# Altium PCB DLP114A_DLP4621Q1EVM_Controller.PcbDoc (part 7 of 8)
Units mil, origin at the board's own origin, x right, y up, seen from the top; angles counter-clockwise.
Board outline 4803.15 x 2598.43 mil, 14 copper layers (Top Layer, GND 1, SIGNAL 1, GND 2, SIGNAL 2, PWR SPLIT PLANE 1, GND 3, GND 4, PWR SPLIT PLANE 2, SIGNAL 3, GND 5, SIGNAL 4, GND 6, Bottom Layer), stack 91.4 mil thick; 489 components, 394 nets, 1925 pads, 1273 vias.
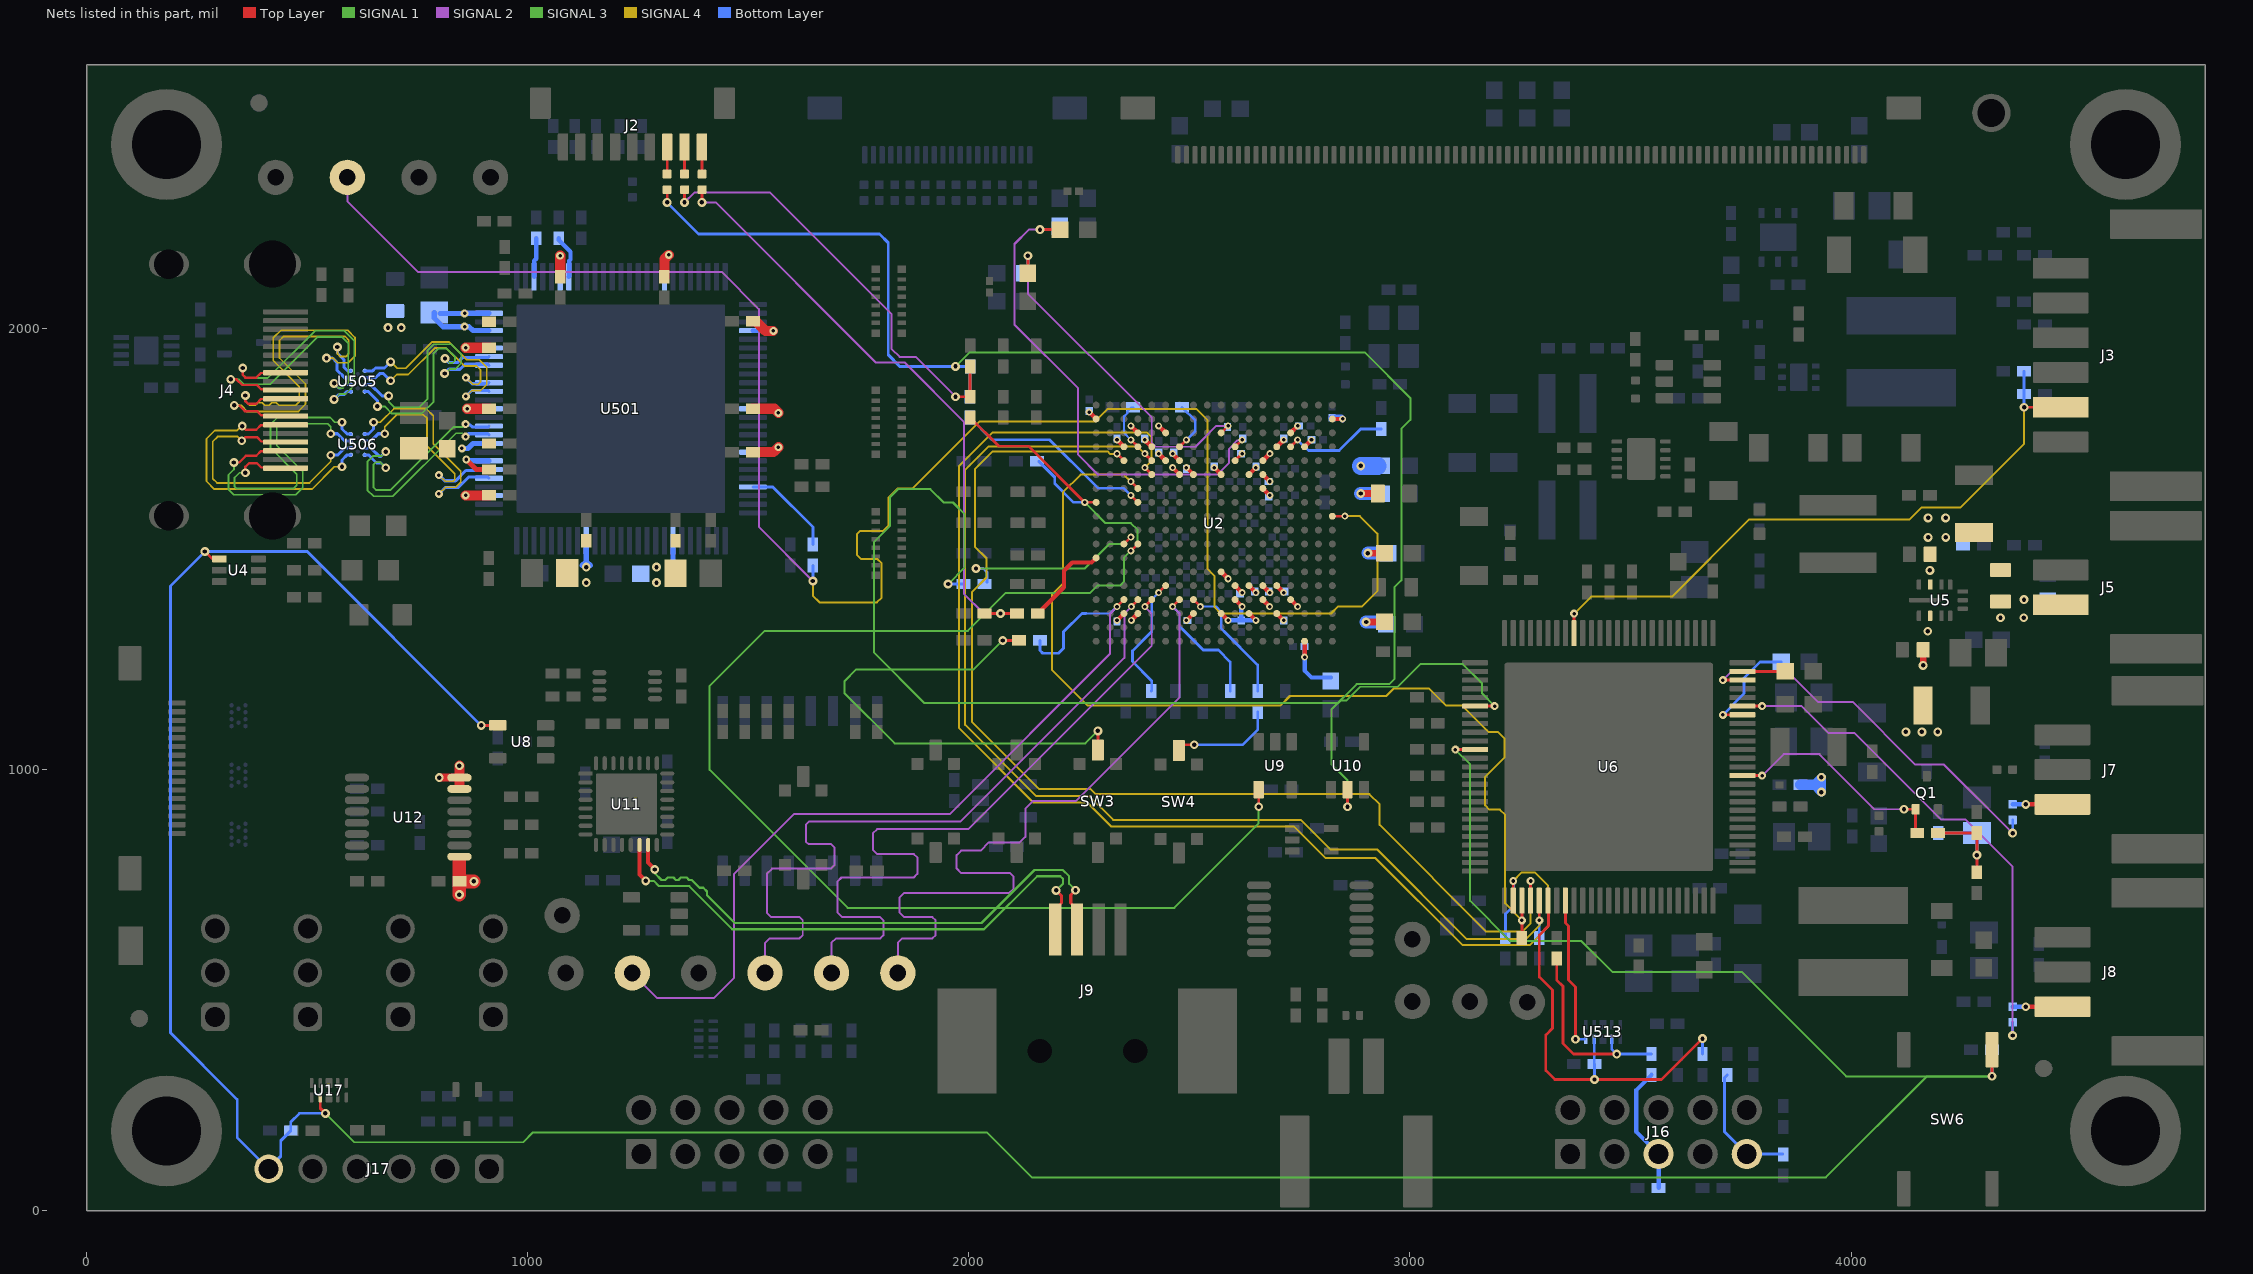
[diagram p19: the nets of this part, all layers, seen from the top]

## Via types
v1: diameter 20, hole 10, Top Layer to Bottom Layer, tented top, 716 vias
v2: diameter 16, hole 8, Top Layer to Bottom Layer, 234 vias
v3: diameter 19.68, hole 7.87, Top Layer to Bottom Layer, 170 vias
v4: diameter 18, hole 8, Top Layer to Bottom Layer, tented top, 78 vias
v5: diameter 18, hole 8, Top Layer to Bottom Layer, tented bottom, 51 vias
v6: diameter 39.37, hole 19.68, Top Layer to Bottom Layer, 24 vias

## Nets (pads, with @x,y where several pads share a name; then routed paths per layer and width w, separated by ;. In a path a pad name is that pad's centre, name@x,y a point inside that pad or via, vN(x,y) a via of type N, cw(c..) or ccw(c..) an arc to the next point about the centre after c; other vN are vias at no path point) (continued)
PMIC_SPI2_CSZ0: U6.33 U513.5 | length 344.7
  Top Layer w6.3: U6.33@3352.25,703.17 3352.25,652.44 3359.35,645.34 3359.35,523 3375.12,507.23 v1(3375.12,388.98)
  Bottom Layer w6.3: v1(3375.12,388.98) U513.5@3396.16,388.98
PMIC_SPI2_CSZ_S: C624.1 J16.9 R588.1 | length 284.7
  Bottom Layer w6.3: R588.1@3719.2,308.17 3712.85,301.82 3712.85,179.37 J16.9@3763.48,128.74 C624.1@3845.19,128.74
PMIC_SPI2_PICO: R589.2 R591.2 U6.31 U513.4 | length 941.5
  Top Layer w6.3: U6.31@3312.88,703.17 3313.78,702.26 3313.78,667.57 3314.07,667.29 3314.07,646.18 3293.19,625.31 3293.19,530.39 3323.18,500.4 3323.18,413.85 3307.98,398.66 3307.98,318.07 3328.33,297.72 v1(3418.39,297.72) 3570.45,297.72 v1(3663.2,390.47)
  Bottom Layer w6.3: U513.4@3417.86,388.98 3417.86,369.98 3417.86,333.3 R591.2@3418.39,332.78 v1(3418.39,297.72) ; R589.2@3663.2,355.41 v1(3663.2,390.47)
PMIC_SPI2_POCI: R62.1 R587.2 U513.2 | length 447.4
  Top Layer w6.3: R62.1@3332.56,571.67 3332.56,523.2 3346.58,509.18 3346.58,379.28 3370.44,355.42 v1(3468.88,355.42)
  Bottom Layer w6.3: U513.2@3457.23,388.98 3457.23,367.07 v1(3468.88,355.42) R587.2@3547.48,355.42
PMIC_SPI2_POCI_S: C628.1 J16.5 R587.1 | length 291.1
  Bottom Layer w10: R587.1@3547.48,308.17 3513.29,273.98 3513.29,178.93 J16.5@3563.48,128.74 C628.1@3563.48,52.01
PMIC_SPI_CLK: R575.2 U2.F5 U6.27 | length 3093.6
  Top Layer w6.3: v2(2398.81,1684.87) U2.F5@2414.56,1669.12 ; U6.27@3234.14,703.17 v4(3234.14,747.7)
  SIGNAL 4 w4.5: v2(2398.81,1684.87) 2414.56,1700.62 2414.56,1753.68 2404.27,1763.97 2053.39,1763.97 1978.03,1688.61 1978.03,1094.02 2146.35,925.71 2268.64,925.71 2323.34,871.01 2737.3,871.01 2808.62,799.69 2921.85,799.69 3119.2,602.34 3271.15,602.34 3313.41,644.59 3313.41,736.48 3282.72,767.17 3253.61,767.17 v4(3234.14,747.7)
  Bottom Layer w6.3: R575.2@3216.44,618.91 3216.44,673.27 3234.53,691.36 3234.53,747.3 v4(3234.14,747.7)
PMIC_SPI_CSZ0: R61.2 U2.G4 U6.28 | length 2297.4
  Top Layer w6.3: v2(2367.31,1653.38) U2.G4@2383.06,1637.63 ; R61.2@3253.82,618.91 v4(3253.82,658.64) U6.28@3253.82,703.17
  SIGNAL 4 w4.5: v2(2367.31,1653.38) 2351.55,1669.14 2253.45,1669.14 2213.22,1628.91 2213.22,1421.85 2188.15,1396.78 2188.15,1227.05 2269.71,1145.49 2706.38,1145.49 2727.98,1167.09 2945.74,1167.09 2962.6,1183.95 3043.48,1183.95 3082.07,1145.35 3118.22,1145.35 3178.36,1085.22 3199.78,1085.22 3213.78,1071.21 3213.78,1027.3 3170.14,983.66 3170.14,919.07 3179.75,909.45 3203.57,909.45 3215.56,897.47 3215.56,696.9 v4(3253.82,658.64)
PMIC_SPI_PICO: R574.2 U2.E5 U6.30 | length 2647.3
  Top Layer w6.3: v2(2398.81,1716.37) U2.E5@2414.56,1700.62 ; v4(3293.19,658.64) U6.30@3293.19,703.17
  SIGNAL 4 w4.5: v2(2398.81,1716.37) 2382.76,1732.42 2044.37,1732.42 1991.58,1679.63 1991.58,1101.7 2152.99,940.29 2273.36,940.29 2327.16,886.49 2752.05,886.49 2819.33,819.22 2925.23,819.22 3127.87,616.58 3263.22,616.58 3293.19,646.55 v4(3293.19,658.64)
  Bottom Layer w6.3: R574.2@3293.19,618.91 v4(3293.19,658.64)
PMIC_SPI_POCI: U2.E3 U6.29 | length 2598.8
  Top Layer w6.3: v2@2335.89,1716.23 U2.E3@2351.5,1700.62 ; U6.29@3273.51,703.17 v4(3273.51,747.7)
  SIGNAL 4 w4.5: v2(2335.82,1716.23) 2319.67,1716.23 2314.47,1721.43 2053.99,1721.43 2013.74,1681.18 2013.74,1505.42 2040,1479.15 2040,1435.74 2007.24,1402.98 2007.24,1108 2159.16,956.08 2276.05,956.08 2287.58,944.55 2908.07,944.55 2930.99,921.63 2930.99,874.82 3172.18,633.63 3255.6,633.63 3273.7,651.73 v4@3273.7,747.51
PMIC_TIA_PD1: L525.1 U6.73 | length 891.3
  Top Layer w6.3: v4(3709.3,1203.17) U6.73@3753.82,1203.17
  SIGNAL 2 w4.5: v4(3709.3,1203.17) 3728.98,1222.85 3855.64,1222.85 3924.74,1153.75 4003.55,1153.75 4145.57,1011.73 4210.64,1011.73 v1(4366.2,856.17)
  Bottom Layer w6.3: v1(4366.2,856.17) L525.1@4366.19,886.04
PMIC_TIA_PD1_FILT: C39.1 U6.74 | length 97
  Top Layer w6.3: U6.74@3753.82,1222.85 C39.1@3850.84,1222.85
PMIC_TIA_PD2: L526.1 U6.70 | length 1175.4
  Top Layer w6.3: U6.70@3753.82,1144.11 v4(3798.35,1144.11)
  SIGNAL 2 w4.5: v4(3798.35,1144.11) 3888.03,1144.11 3949.16,1082.98 4008.06,1082.98 4203.35,887.68 4258.35,887.68 4366.13,779.9 v1(4366.13,397.48)
  Bottom Layer w6.3: v1(4366.13,397.48) L526.1@4366.11,427.36
PMIC_TIA_PD2_FILT: C589.1 U6.69 | length 247.3
  Top Layer w6.3: v4(3709.3,1124.43) U6.69@3753.82,1124.43
  Bottom Layer w6.3: v4(3709.3,1124.43) 3757.37,1172.51 3757.37,1207.89 3793.88,1244.4 C589.1@3841.62,1244.4
PMIC_VIN_N8V: Q1.1 R55.1 U6.62 | length 519.5
  Top Layer w6.3: U6.62@3753.82,986.63 v4(3798.35,986.63) ; v1(4119.86,910.37) Q1.1@4146.11,910.37 4146.11,860.55 R55.1@4150.05,856.62
  SIGNAL 2 w4.5: v4(3798.35,986.63) 3846.87,1035.15 3928.07,1035.15 4052.85,910.37 v1(4119.86,910.37)
PMIC_WD1: R546.2 U6.6 | length 2365
  Top Layer w6.3: U6.6@3147.52,1144.11 v4(3192.05,1144.11)
  SIGNAL 1 w4.5: v1(1953.03,1420.91) 1990.67,1458.55 1990.67,1579.1 1964.04,1605.73 1943.34,1605.73 1912.99,1636.08 1839.37,1636.08 1821.54,1618.24 1821.54,1553.16 1785.09,1516.71 1785.09,1265.51 1899.38,1151.22 2837.17,1151.22 2842.75,1156.8 2855.83,1156.8 2887.1,1188.07 2972.03,1188.07 3023.49,1239.54 3119.81,1239.54 3163.25,1196.1 3163.25,1172.91 v4(3192.05,1144.11)
  Bottom Layer w6.3: v1(1953.03,1420.91) R546.2@1987.78,1420.91
PMIC_WD1_S: R546.1 U2.L3 | length 454.6
  Top Layer w6.3: U2.L3@2351.57,1511.64 v2(2367.31,1527.39)
  SIGNAL 1 w4.5: v1(2016.18,1456.12) 2262.47,1456.12 2317.99,1511.64 2351.56,1511.64 v2(2367.31,1527.39)
  Bottom Layer w6.3: v1(2016.18,1456.12) 2032.97,1456.12 2041.42,1447.66 R546.1@2041.42,1424.76
PROJ_ON: C622.1 J17.6 R585.1 SW6.1 U4.1 U6.11 U8.4 U17.2 | length 8465.1
  Top Layer w6.3: v1(268.25,1494.75) 285.28,1477.72 U4.1@300.17,1477.72 ; U17.2@529.68,257.02 529.68,232.66 v1(541.33,221.01) ; v1(894.49,1100.52) U8.4@932.17,1100.52 ; v4(3103,1045.69) U6.11@3147.52,1045.69 ; v1(4319.39,305.03) SW6.1@4319.39,365.19
  SIGNAL 1 w4.5: v1(541.33,221.01) 606.85,155.49 989.53,155.49 1011.96,177.91 2040.76,177.91 2142.99,75.68 3942.74,75.68 4172.1,305.03 v1(4319.39,305.03)
  SIGNAL 3 w4.5: v4(3103,1045.69) 3136.21,1012.47 3136.21,702.8 3227.52,611.49 3388.78,611.49 3458.78,541.49 3752.28,541.49 3988.74,305.03 v1(4319.39,305.03)
  Bottom Layer w6.3: J17.6@412.58,95.27 341.29,166.56 341.29,252.24 189.91,403.62 189.91,1416.42 v1(268.25,1494.75) 500.26,1494.75 v1(894.49,1100.52) ; J17.6@412.58,96.27 440.15,123.85 440.15,159 462.75,181.6 C622.1@462.75,182.03 462.75,201.5 482.27,221.01 v1(541.33,221.01) ; v1(4319.39,305.03) R585.1@4319.39,365.19
PWM0_DVR_EN_S: R523.1 U2.H4 | length 460.4
  Top Layer w6.3: v2(2367.31,1621.88) U2.H4@2383.06,1606.13
  Bottom Layer w5.4: 2283.65,1647.42 2293.44,1637.63 2351.56,1637.63 v2(2367.31,1621.88)
  Bottom Layer w6.3: R523.1@2002.26,1798.32 2052.61,1747.96 2183.11,1747.96 2283.65,1647.42
PWM0_OUT_DRV_EN_IN: FB1.1 R512.2 R523.2 U10.2 | length 3271.2
  Top Layer w6.3: v1(1316.06,2286.1) FB1.1@1316.06,2314.95 ; v1(2858.34,916.15) U10.2@2858.34,954.84
  SIGNAL 3 w4.5: v1(1969.81,1914.32) 2001.82,1946.32 2897.06,1946.32 3000.71,1842.67 3000.71,1793.29 2980.25,1772.82 2980.25,1429.39 2965.12,1414.27 2965.12,1206.08 2953.11,1194.06 2879.16,1194.06 2822.04,1136.94 2822.04,1012.86 2858.34,976.56 v1(2858.34,916.15)
  Bottom Layer w6.3: v1(1316.06,2286.1) 1387.53,2214.63 1797.05,2214.63 1817.18,2194.5 1817.18,1940.58 1843.44,1914.32 v1(1969.81,1914.32) R512.2@2002.79,1914.32 ; R523.2@2002.52,1845.82 R512.2@2002.52,1914.05
PWM0_OUT_F: FB1.2 J2.7 | length 61.2
  Top Layer w6.3: FB1.2@1316.06,2350.38 J2.7@1316.06,2411.61
PWM1_COMPOUT_S: R10.1 R529.2 U2.H1 U2.L4 U9.4 | length 3572.2
  Top Layer w6.3: R10.1@2002.79,1798.32 2067.7,1733.41 2135.49,1733.41 v2(2262.77,1606.13) U2.H1@2288.57,1606.13 ; v2(2367.31,1495.9) U2.L4@2383.06,1511.64 ; v1(2657.05,916.15) U9.4@2657.05,954.84
  SIGNAL 1 w4.5: v2(2262.77,1606.13) 2309.76,1559.14 2367.06,1559.14 2382.56,1543.64 2382.56,1511.21 ; v2(2367.31,1495.9) 2382.63,1511.21
  SIGNAL 3 w4.5: v2(2367.31,1495.9) 2351.64,1480.22 2351.64,1426.19 2342.6,1417.16 2291.07,1417.16 2274.79,1400.88 2083.93,1400.88 1997.71,1314.66 1536.92,1314.66 1412.35,1190.09 1412.35,999.72 1725.05,687.03 2465.76,687.03 2656.96,878.23 v1@2656.96,916.06
  Bottom Layer w6.3: R529.2@2158.35,1699.32 2194.79,1662.88 2194.79,1648.88 2237.54,1606.13 v2(2262.77,1606.13)
PWM1_OUT_COMPOUT_IN: FB2.1 R6.2 R10.2 | length 992.7
  Top Layer w6.3: v1(1355.43,2286.1) FB2.1@1355.43,2314.95 ; v1(1969.81,1845.56) R10.2@2002.79,1845.56 R6.2@2002.79,1914.32
  SIGNAL 2 w4.5: v1(1355.43,2286.1) 1378.21,2308.89 1549.02,2308.89 1825.12,2032.79 1825.12,1953.6 1842.9,1935.82 1879.55,1935.82 v1(1969.81,1845.56)
PWM1_OUT_F: FB2.2 J2.8 | length 61.2
  Top Layer w6.3: FB2.2@1355.43,2350.38 J2.8@1355.43,2411.61
PWM2_OUT: FB3.1 R35.2 R36.2 | length 1394
  Top Layer w6.3: v1(1394.8,2286.1) FB3.1@1394.8,2314.95 ; R35.2@2035.02,1354.08 v1(2071.77,1354.08) R36.2@2108.89,1354.08
  SIGNAL 2 w4.5: v1@1394.98,2286.29 1426.19,2286.29 1789.34,1923.14 1854.52,1923.14 1988.93,1788.73 1988.93,1398.8 2033.65,1354.08 v1(2071.77,1354.08)
PWM2_OUT_F: FB3.2 J2.9 | length 61.2
  Top Layer w6.3: FB3.2@1394.8,2350.38 J2.9@1394.8,2411.61
PWM2_OUT_S: R36.1 U2.M1 | length 206.7
  Top Layer w10: R36.1@2156.13,1354.08 2215.74,1413.7 2215.74,1451.26 2234.15,1469.67 2278.1,1469.67 U2.M1@2288.57,1480.15
RED_LED_THERM: C523.1 J3.2 R519.1 U6.92 | length 1471.5
  Top Layer w6.3: U6.92@3371.93,1309.47 v4(3371.93,1354) ; v1(4392.2,1821.69) J3.2@4475.2,1821.69
  SIGNAL 4 w4.5: v4(3371.93,1354) 3410.43,1392.5 3593.94,1392.5 3769.14,1567.69 4132.89,1567.69 4160.1,1594.91 4248.06,1594.91 4392.2,1739.06 v1(4392.2,1821.69)
  Bottom Layer w6.3: v1(4392.2,1821.69) C523.1@4392.2,1851.69 R519.1@4392.2,1903.25
RPI_0: R525.2 U2.D15 | length 242.4
  Top Layer w6.3: U2.D15@2729.52,1732.12 v2(2745.27,1747.86)
  Bottom Layer w6.3: v2(2745.27,1747.86) 2769.68,1723.45 2839.52,1723.45 2888.4,1772.33 R525.2@2935.04,1772.33
RPI_1: R528.2 U2.D4 | length 113.3
  Top Layer w6.3: v2(2367.31,1747.86) U2.D4@2383.06,1732.12
  Bottom Layer w5: v2(2367.31,1747.86) 2351.59,1763.59 2351.59,1800.55 2359.21,1808.17 2359.21,1812.1 2368.52,1821.42 R528.2@2372.45,1821.42
RPI_LS: R527.2 U2.D7 | length 116.6
  Top Layer w6.3: U2.D7@2477.55,1732.12 v2(2493.3,1747.86)
  Bottom Layer w6.3: R527.2@2483.36,1821.42 2513.44,1791.34 2513.44,1768.01 v2(2493.3,1747.86)
RXCLK_N: U501.94 U505.C4 | length 513.3
  SIGNAL 1 w4: v1(659.12,1823.53) 675.51,1823.53 691.47,1807.57 759.79,1807.57 786.66,1834.43 786.66,1944.38 796.98,1954.71 816.44,1954.71 835.4,1935.75 835.4,1927.76 829.72,1922.08 822.56,1922.08 v1(812.37,1932.27)
  Bottom Layer w7: U505.C4@630.52,1857.06 638.91,1857.06 659.12,1836.85 v1(659.12,1823.53) ; v1(812.37,1932.27) 821.91,1922.73 840.44,1922.73 851.78,1934.08 909.76,1934.08 U501.94@912.1,1936.43
RXCLK_N_S: J4.12 U505.A4 | length 650.5
  Top Layer w5.4: v1(353.88,1910.71) 353.88,1894.93 360.01,1888.8 384.62,1888.8 395.22,1899.41 450.54,1899.41 J4.12@451.18,1900.05
  SIGNAL 1 w4: v1(353.88,1910.71) 353.88,1895.76 361.74,1887.9 410.8,1887.9 518.08,1995.18 584.01,1995.18 606.87,1972.32 606.87,1871.57 586.91,1851.61 573.22,1851.61 v1(561.07,1839.46)
  Bottom Layer w7: v1(561.07,1839.46) 571.76,1850.15 582.97,1850.15 589.88,1857.06 U505.A4@599.02,1857.06
RXCLK_P: U501.93 U505.C3 | length 557
  SIGNAL 1 w4: v1(684.72,1847.5) 684.72,1834.12 697.27,1821.57 754,1821.57 772.66,1840.23 772.66,1950.18 787.09,1964.61 826.34,1964.61 849.4,1941.55 849.4,1921.96 835.52,1908.08 823.06,1908.08 v1@813.17,1898.2
  Bottom Layer w7: U505.C3@630.52,1872.81 644.37,1872.81 669.68,1847.5 ; 669.73,1847.45 669.68,1847.5 ; v1(684.72,1847.5) 669.68,1847.5 ; v1(811.58,1898.2) 821.11,1907.73 846.65,1907.73 858,1919.08 909.76,1919.08 U501.93@912.1,1916.74
RXCLK_P_S: J4.10 U505.A3 | length 630.9
  Top Layer w5.4: v1(326.95,1884.94) 340.11,1884.94 353.05,1872 386.23,1872 396.07,1862.17 449.7,1862.17 J4.10@451.18,1860.68
  SIGNAL 1 w4: v1(326.95,1884.94) 344.91,1884.94 355.94,1873.9 416.6,1873.9 523.88,1981.18 578.21,1981.18 592.87,1966.52 592.87,1877.37 581.11,1865.61 571.3,1865.61 v1(561.07,1875.84)
  Bottom Layer w7: v1(561.07,1875.84) 571.76,1865.15 576.76,1865.15 584.42,1872.81 U505.A3@599.02,1872.81
RXIN0_N: U501.91 U505.C2 | length 452.3
  SIGNAL 4 w4: v1(689.13,1881.75) 703.24,1895.85 729.35,1895.85 789.27,1955.77 815.52,1955.77 855.87,1915.41 883.97,1915.41 892.95,1906.44 892.95,1879.1 887.46,1873.61 875.15,1873.61 v5(859.8,1888.96)
  Bottom Layer w7: U505.C2@630.52,1888.56 654.92,1888.56 664.27,1897.9 672.97,1897.9 v1(689.13,1881.75) ; v5(859.8,1888.96) 873.73,1875.03 909.76,1875.03 U501.91@912.1,1877.37
RXIN0_N_S: J4.9 U505.A2 | length 832.2
  Top Layer w5.4: v1(359.89,1848.29) 359.89,1835.66 365.81,1829.74 384.62,1829.74 395.22,1840.35 450.54,1840.35 J4.9@451.18,1841
  SIGNAL 4 w4: v1(359.89,1848.29) 359.89,1835.83 369.59,1826.14 382.11,1826.14 388.11,1832.14 398.11,1832.14 404.11,1826.14 414.11,1826.14 420.11,1832.14 430.11,1832.14 436.11,1826.14 474.39,1826.14 482.26,1834.01 482.26,1868.53 423.25,1927.54 423.25,1978.82 440.7,1996.28 591.63,1996.28 608.19,1979.72 608.19,1937.35 593.42,1922.58 569.28,1922.58 558.72,1933.14 v1(543.9,1933.14)
  Bottom Layer w7: v1(543.9,1933.14) 557.68,1933.14 567.34,1923.49 567.34,1906.29 585.07,1888.56 U505.A2@599.02,1888.56
RXIN0_P: U501.90 U505.C1 | length 496
  SIGNAL 4 w4: v1(689.13,1924.61) 703.89,1909.85 723.56,1909.85 783.47,1969.77 821.32,1969.77 861.67,1929.41 889.77,1929.41 906.95,1912.24 906.95,1873.3 893.26,1859.61 873.31,1859.61 v5(859.8,1846.09)
  Bottom Layer w7: U505.C1@630.52,1904.3 648.4,1904.3 654.9,1910.8 675.32,1910.8 v1(689.13,1924.61) ; v5(859.8,1846.09) 873.73,1860.03 909.76,1860.03 U501.90@912.1,1857.69
RXIN0_P_S: J4.7 U505.A1 | length 781.2
  Top Layer w5.4: v1(334.68,1825.77) 346.03,1825.77 358.85,1812.94 386.23,1812.94 396.07,1803.11 449.69,1803.11 J4.7@451.18,1801.63
  SIGNAL 4 w4: v1(334.68,1825.77) 350.15,1825.77 363.79,1812.14 480.19,1812.14 496.26,1828.21 496.26,1874.32 437.25,1933.34 437.25,1973.02 446.5,1982.28 585.83,1982.28 594.19,1973.92 594.19,1943.15 587.62,1936.58 575.08,1936.58 569.03,1942.62 v1@569.03,1957.84
  Bottom Layer w7: v1(568.6,1958.27) 568.6,1944.49 583.08,1930.01 583.08,1912.81 591.59,1904.3 U505.A1@599.02,1904.3
RXIN1_N: U501.86 U506.C4 | length 476.6
  SIGNAL 1 w4: v1(678.2,1684.64) 665.95,1696.9 655.13,1696.9 650.56,1692.33 650.56,1639.64 656.38,1633.82 688.59,1633.82 831.5,1776.72 852.53,1776.72 v5(859.13,1783.32)
  Bottom Layer w7: U506.C4@630.52,1713.65 638.91,1713.65 657.22,1695.33 667.51,1695.33 v1(678.2,1684.64) ; v5(859.13,1783.32) 861.23,1781.22 870.08,1781.22 874.21,1777.1 909.27,1777.1 909.76,1776.6 U501.86@912.1,1778.95
RXIN1_N_S: J4.6 U506.A4 | length 668.7
  Top Layer w5.4: v1(352.82,1778.84) 360.97,1770.69 384.62,1770.69 395.22,1781.3 450.54,1781.3 J4.6@451.18,1781.94
  SIGNAL 4 w4: v1@350.89,1778.84 341.21,1769.16 291.1,1769.16 271.84,1749.9 271.84,1654.14 289.77,1636.21 510.98,1636.21 561.69,1686.91 v1(579.02,1686.91)
  Bottom Layer w7: v1(579.02,1686.91) 579.02,1702.03 590.63,1713.65 U506.A4@599.02,1713.65
RXIN1_P: U501.85 U506.C3 | length 522.6
  SIGNAL 1 w4: v1(678.2,1721.03) 668.08,1710.9 649.33,1710.9 636.56,1698.13 636.56,1633.84 650.58,1619.82 694.39,1619.82 837.3,1762.72 851.73,1762.72 v5(859.13,1755.32)
  Bottom Layer w7: U506.C3@630.52,1729.39 644.37,1729.39 663.43,1710.33 667.51,1710.33 v1(678.2,1721.03) ; v5(859.13,1755.32) 865.41,1761.6 909.76,1761.6 U501.85@912.1,1759.26
RXIN1_P_S: J4.4 U506.A3 | length 624.4
  Top Layer w5.4: v1(351.86,1745.74) 360,1753.89 386.23,1753.89 396.07,1744.06 449.7,1744.06 J4.4@451.18,1742.57
  SIGNAL 4 w4: v1(351.86,1745.74) 342.45,1755.16 296.9,1755.16 285.84,1744.1 285.84,1659.94 295.56,1650.21 505.18,1650.21 553.65,1698.67 v1(553.65,1713)
  Bottom Layer w7: v1(553.65,1713) 568.77,1713 585.17,1729.39 U506.A3@599.02,1729.39
RXIN2_N: U501.81 U506.C2 | length 515.8
  SIGNAL 4 w4: v1(675.89,1761.54) 675.89,1777.8 702.82,1804.73 763.53,1804.73 771.9,1796.35 771.9,1733.1 834.33,1670.67 834.33,1657.53 830.96,1654.16 812.61,1654.16 v5(798.73,1668.04)
  Bottom Layer w7: U506.C2@630.52,1745.14 644.37,1745.14 660.77,1761.54 v1(675.89,1761.54) ; v5(798.73,1668.04) 811.69,1655.08 836.6,1655.08 859.7,1678.18 909.76,1678.18 U501.81@912.1,1680.52
RXIN2_N_S: J4.3 U506.A2 | length 732.9
  Top Layer w5.4: v1(333.93,1696.44) 345.89,1696.44 361.08,1711.63 384.62,1711.63 395.22,1722.24 450.54,1722.24 J4.3@451.18,1722.89
  SIGNAL 1 w4: v1(333.93,1696.44) 333.93,1680.59 321.54,1668.2 321.54,1635.69 333.98,1623.25 474.01,1623.25 490.13,1639.37 490.13,1675.97 431.08,1735.01 431.08,1776.95 438.45,1784.32 546.41,1784.32 553.65,1777.08 v1(553.65,1761.54)
  Bottom Layer w7: v1(553.65,1761.54) 568.77,1761.54 585.17,1745.14 U506.A2@599.02,1745.14
RXIN2_P: U501.80 U506.C1 | length 562
  SIGNAL 4 w4: v1(650.52,1787.62) 665.92,1787.62 697.02,1818.73 769.33,1818.73 785.9,1802.15 785.9,1738.9 848.33,1676.47 848.33,1651.73 836.76,1640.16 813.71,1640.16 v5(798.73,1625.17)
  Bottom Layer w7: U506.C1@630.52,1760.89 638.91,1760.89 650.52,1772.5 v1(650.52,1787.62) ; v5(798.73,1625.17) 813.64,1640.08 842.81,1640.08 865.91,1663.18 909.76,1663.18 U501.80@912.1,1660.84
RXIN2_P_S: J4.1 U506.A1 | length 682.8
  Top Layer w5.4: v1(359.92,1673.34) 359.92,1686.72 368.04,1694.83 386.23,1694.83 396.07,1685 449.7,1685 J4.1@451.18,1683.52
  SIGNAL 1 w4: v1(359.92,1673.34) 346.48,1673.34 335.54,1662.4 335.54,1641.76 340.05,1637.25 468.21,1637.25 476.13,1645.17 476.13,1670.17 417.08,1729.22 417.08,1782.75 432.65,1798.32 552.21,1798.32 562.9,1787.62 v1(579.02,1787.62)
  Bottom Layer w7: v1(579.02,1787.62) 579.02,1772.5 590.63,1760.89 U506.A1@599.02,1760.89
SPI0_DIR1: R60.1 U12.1 U12.7 U12.8 | length 206.7
  Top Layer w17.7: v1(799.5,982.02) U12.8@845.06,982.02
  Top Layer w23: U12.7@845.06,959.62 U12.8@845.06,982.02 v1(845.06,1008.88)
  Top Layer w31: v1(845.06,716.91) R60.1@845.06,746.73 ; U12.1@845.06,795.98 R60.1@845.06,746.73 ; v1(877.87,746.73) R60.1@845.06,746.73
SPIMD_PU: R38.2 SW3.1 | length 1137.7
  Top Layer w6.3: v1(2076.68,1293.01) R38.2@2113.89,1293.01 ; SW3.1@2292.55,1044.67 v1(2292.55,1088.07)
  SIGNAL 3 w4.5: v1(2076.68,1293.01) 2011.08,1227.41 1745.13,1227.41 1718.11,1200.38 1718.11,1173.55 1831.97,1059.69 2264.17,1059.69 v1(2292.55,1088.07)
ST: R503.1 U501.3 | length 89.3
  Bottom Layer w10: U501.3@1014.46,2117.53 1014.46,2153.49 1019.46,2158.49 R503.1@1019.46,2204.73
STAGZ: R502.1 U501.7 | length 99.7
  Bottom Layer w10: R502.1@1070.46,2204.73 1070.46,2200.79 1096.92,2174.34 1096.92,2156.54 1094.11,2153.73 1094.11,2118.43 U501.7@1093.21,2117.53
TESTPT0: R549.1 TP8.1 U2.R3 | length 1969.8
  Top Layer w6.3: v2(2335.82,1369.91) U2.R3@2351.57,1385.66
  SIGNAL 2 w4.5: TP8.1@1236.97,539.32 1294.11,482.18 1421.29,482.18 1467.68,528.56 1467.68,764.03 1603.16,899.51 1957.03,899.51 2319.95,1262.43 2319.95,1354.04 v2(2335.82,1369.91)
  Bottom Layer w5.4: 2265.93,1354.36 2266.18,1354.36 2266.32,1354.21 2320.12,1354.21 v2(2335.82,1369.91)
  Bottom Layer w6.3: R549.1@2161.13,1293.01 2161.13,1270.33 2167.52,1263.94 2203.44,1263.94 2214.74,1275.25 2214.74,1312.69 2256.22,1354.16 2265.73,1354.16
TESTPT1: TP10.1 U2.R4 | length 1703
  Top Layer w6.3: v2@2368.21,1370.27 U2.R4@2383.06,1385.12
  SIGNAL 2 w4.5: TP10.1@1537.99,539.32 1537.99,607.28 1548.39,617.68 1616.12,617.68 1623.46,625.03 1623.46,658.63 1616.43,665.66 1552.35,665.66 1542.01,676.01 1542.01,763.88 1553.94,775.82 1687.15,775.82 1695.6,784.27 1695.6,823.13 1687.61,831.12 1636.67,831.12 1630.62,837.17 1630.62,875.56 1637.24,882.18 1980.91,882.18 2352.39,1253.66 2352.39,1353.92 v2(2368.21,1369.74)
TESTPT2: TP11.1 U2.R5 | length 1704.2
  Top Layer w6.3: v2@2398.81,1369.83 U2.R5@2414.56,1385.57
  SIGNAL 2 w4.5: TP11.1@1688.5,539.32 1688.5,607.28 1698.9,617.68 1799.37,617.68 1806.02,624.33 1806.02,658.43 1798.78,665.66 1712.73,665.66 1701.82,676.57 1701.82,746.13 1711.33,755.64 1874.69,755.64 1883.07,764.02 1883.07,801.2 1875.56,808.71 1792.7,808.71 1782.54,818.88 1782.54,855.81 1792.09,865.37 1998.87,865.37 2414.6,1281.1 2414.6,1353.95 v2(2398.81,1369.74)
TESTPT3: R557.1 TP12.1 U2.R7 | length 1979.7
  Top Layer w6.3: v2(2461.8,1369.91) U2.R7@2477.55,1385.66
  SIGNAL 2 w4.5: TP12.1@1839.01,539.32 1839.01,607.28 1849.41,617.68 1917.14,617.68 1924.48,625.03 1924.48,658.63 1917.45,665.66 1853.37,665.66 1843.1,675.93 1843.1,710.63 1853.09,720.62 2092.11,720.62 2101.63,730.15 2101.63,757.57 2093.1,766.1 1982.03,766.1 1972.05,776.08 1972.05,806.11 1982.4,816.46 2026.57,816.46 2045.46,835.36 2115.27,835.36 2127.92,848.01 2127.92,911.92 2144.76,928.77 2241.99,928.77 2477.84,1164.62 2477.84,1236.24 2477.84,1353.87 v2(2461.8,1369.91)
  Bottom Layer w5.4: v2(2461.8,1369.91) 2475.71,1356 ; 2469.28,1362.44 2475.71,1356 ; 2484.9,1317.57 2477.5,1324.96 2477.5,1354.21 2475.71,1356
  Bottom Layer w6.3: 2484.9,1317.57 2531.32,1271.15 2565.5,1271.15 2592.39,1244.25 R557.1@2592.39,1178.31
TESTPT5: R556.1 U2.R8 | length 288.3
  Top Layer w6.3: U2.R8@2509.05,1385.66 v2(2524.79,1369.91)
  Bottom Layer w5.4: v2(2524.79,1369.91) 2559.98,1369.91 2571.99,1357.9 2571.99,1320.31 2578.36,1313.94
  Bottom Layer w6.3: 2578.36,1313.94 2654.71,1237.59 R556.1@2654.71,1178.31
TESTPT6: R553.1 U2.P6 | length 288.4
  Top Layer w6.3: v2(2430.31,1401.41) U2.P6@2446.05,1417.16
  Bottom Layer w5.4: 2414.56,1325.65 2414.56,1385.66 v2(2430.31,1401.41)
  Bottom Layer w6.3: R553.1@2413.24,1178.6 2414.56,1179.92 2414.56,1201.18 2370.74,1245 2370.74,1269.49 2414.56,1313.31 2414.56,1325.65
TIA_PD1_FIL: J7.1 L525.2 | length 122.1
  Top Layer w10: v1(4396.03,921.49) J7.1@4488.19,921.49
  Bottom Layer w10: L525.2@4366.17,921.49 v1(4396.03,921.49)
TIA_PD2_FIL: J8.1 L526.2 | length 113
  Top Layer w10: v1(4395.97,462.79) J8.1@4479.13,462.79
  Bottom Layer w10: L526.2@4366.11,462.79 v1(4395.97,462.79)
TP5_PU: R556.2 SW4.1 | length 242
  Top Layer w6.3: SW4.1@2476.09,1043.49 2476.09,1049.15 2483.71,1056.77 v1(2510.87,1056.77)
  Bottom Layer w6.3: v1(2510.87,1056.77) 2621.08,1056.77 2654.71,1090.4 R556.2@2654.71,1131.06
USBDM: J9.2 U11.15 | length 1263
  Top Layer w7: v1(2241.66,726.83) 2230.98,716.15 2230.98,697.71 2245.08,683.6 J9.2@2245.08,637.8
  Top Layer w9: U11.15@1272.7,829.5 1272.7,789.32 v1(1288.15,773.88)
  SIGNAL 1 w5: v1(1288.15,773.88) 1288.15,765.15 1303.22,750.08 1311.87,750.08 1317.22,755.42 1330.53,755.42 1335.87,750.08 1341.65,750.08 1346.99,755.42 1360.3,755.42 1365.65,750.08 1371.75,750.08 1389.29,732.55 1397.77,732.55 1406.26,724.06 1406.26,715.58 1469.46,652.37 2028.68,652.37 2148.91,772.6 2213.13,772.6 2227.34,758.39 2227.34,741.16 v1(2241.66,726.83)
USBDP: J9.3 U11.14 | length 1263
  Top Layer w7: J9.3@2195.87,637.8 2195.87,683.6 2209.98,697.71 2209.98,714.27 v1(2197.89,726.35)
  Top Layer w9: U11.14@1253.01,829.5 1253.01,762.57 v1(1267.6,747.99)
  SIGNAL 1 w5: v1(1267.6,747.99) 1285.52,747.99 1297.42,736.08 1365.95,736.08 1463.67,638.37 2034.48,638.37 2154.71,758.6 2207.33,758.6 2213.34,752.59 2213.34,741.8 v1(2197.89,726.35)
V_DVI_AVDD: C13.1 C14.1 C16.1 C20.1 C22.1 L1.2 U501.82 U501.84 U501.88 U501.95 | length 384.9
  Top Layer w11.81: v5(860.57,1703.25) 883.31,1680.52 C22.1@912.1,1680.52 ; C13.1@911.81,1956.41 C13.1@912.1,1956.11
  Top Layer w23: v5@859.63,1956.41 C13.1@911.81,1956.41 ; v5(862.37,1818.43) C14.1@912.04,1818.38
  Bottom Layer w11.81: v5(850.57,1728.34) 864.81,1728.34 876.04,1739.58 U501.84@912.1,1739.58 ; v5(859.34,1956.7) 859.93,1956.11 U501.95@912.1,1956.11 ; v5(860.57,1703.25) 863.62,1700.21 U501.82@912.1,1700.21 ; v5(862.37,1818.43) 862.49,1818.32 U501.88@912.1,1818.32
V_DVI_DVDD: C7.1 C15.1 C28.1 C572.1 L3.2 U501.6 U501.38 U501.67 | length 292
  Top Layer w23: C7.1@1073.58,2117.58 v5(1073.63,2165.12) ; C15.1@1510.53,1818.32 1559.1,1818.32 v5(1568.33,1809.09)
  Bottom Layer w10: U501.6@1073.58,2117.58 v5(1073.63,2165.12) ; U501.38@1510.53,1818.32 1559.1,1818.32 v5(1568.33,1809.09)
  Bottom Layer w11.81: 1123.03,1462.8 1132.58,1472.35 ; U501.67@1132.58,1519.1 1132.58,1472.35 ; 1142.12,1462.8 1132.58,1472.35
  other v1: 1132.57,1424.24 1132.57,1459.33
V_DVI_OVDD: C8.1 C10.1 C21.1 C25.1 C29.1 C573.1 L4.2 U501.18 U501.29 U501.43 U501.57 U501.78 | length 509.6
  Top Layer w11.81: v5(859.34,1622.06) v5@859.63,1621.76
  Top Layer w23: v5@859.63,1621.76 C25.1@912.1,1621.76 ; C8.1@1309.74,2117.53 1309.74,2157.05 v5(1319.74,2167.05) ; C21.1@1510.53,1719.89 1510.84,1720.2 1557.54,1720.2 v5(1568.33,1730.99) ; C10.1@1510.53,2016.41 1517.09,2016.41 1538.65,1994.85 v5@1555.68,1994.85
  Bottom Layer w10: U501.18@1309.74,2117.53 1309.74,2157.05 v5(1319.74,2167.05) ; U501.43@1510.53,1719.89 1557.23,1719.89 v5(1568.33,1730.99) ; U501.29@1510.53,1995.48 U501.29@1510.85,1995.16 ; U501.29@1512.16,1994.85 v5(1556.68,1994.85) ; v5@1555.37,1995.16 v5@1555.68,1994.85
  Bottom Layer w11.81: v5@859.34,1621.47 U501.78@912.1,1621.47 ; 1319.92,1464.15 1329.43,1473.66 ; U501.57@1329.43,1519.1 1329.43,1473.66 ; 1338.93,1464.15 1329.43,1473.66
  other v1: 1291.94,1424.24 1291.94,1459.33
V_DVI_PVDD: C11.1 C517.2 L514.2 U501.97 U501.99 | length 259
  Bottom Layer w11.81: L514.2@788.2,2036.25 788.2,2023.76 807.87,2004.09 v5@856.71,2004.09 ; L514.2@801.32,2034.47 v5(856.71,2034.47) ; v5(856.71,2004.47) 856.99,2004.19 867.12,2004.19 875.82,1995.48 U501.97@912.1,1995.48 ; v5@856.71,2034.85 U501.99@912.1,2034.85
  other v1: 683.16,2002.18 713.16,2002.18
VCC3IO_COSC: C542.1 L519.2 U2.E11 | length 61.1
  Top Layer w6.3: U2.E11@2603.53,1700.62 v2(2619.28,1716.37)
  Bottom Layer w40: v1(2888.29,1688.62) L519.2@2927.1,1688.62
VCC11A_DDI: C32.1 C539.1 C540.1 C548.1 C554.1 L522.2 U2.E6 U2.E7 U2.F13 U2.G13 | length 164.5
  Top Layer w10: v2(2430.31,1716.37) U2.E6@2446.05,1700.62 ; v2(2461.8,1716.37) U2.E7@2477.55,1700.62 ; U2.G13@2666.53,1637.63 v2(2682.27,1621.88) ; U2.F13@2666.53,1669.12 v2(2682.27,1653.38)
  Top Layer w15: v1(2904.67,1491.04) C32.1@2942.36,1491.04
  Bottom Layer w30: v1(2904.67,1491.04) L522.2@2942.36,1491.04
VCC11A_LVDS: C36.1 C575.1 C576.1 C577.1 C580.1 L523.2 U2.N10 U2.P11 U2.P12 U2.P13 U2.P14 | length 194.1
  Top Layer w10: U2.N10@2572.04,1448.65 v2(2587.79,1432.9) ; U2.P11@2603.53,1417.16 v2(2619.28,1401.41) ; U2.P12@2635.03,1417.16 v2(2650.78,1401.41) ; U2.P13@2666.53,1417.16 v2(2682.27,1401.41) ; U2.P14@2698.02,1417.16 v2(2713.77,1401.41)
  Top Layer w15: v1(2900.56,1334.92) C36.1@2942.36,1334.92
  Bottom Layer w15: L523.2@2934.4,1334.92 L523.2@2939.4,1329.92
  Bottom Layer w30: v1(2900.56,1334.92) L523.2@2934.4,1334.92
VCC11AD_PLLD: C5.1 C534.1 L515.2 U2.C10 | length 839.4
  Top Layer w6.3: C5.1@2133.94,2125.08 v1(2133.94,2165.29) ; U2.C10@2572.04,1763.61 v2(2587.79,1779.36)
  SIGNAL 2 w4.5: v1(2133.94,2165.29) 2133.94,2079.33 2414.51,1798.76 ; 2414.61,1798.76 2414.61,1741.32 2423.81,1732.12 2513.77,1732.12 2561.01,1779.36 v2(2587.79,1779.36)
  Bottom Layer w6.3: L515.2@2133.94,2125.08 v1(2133.94,2165.29)
VCC11AD_PLLM: C4.1 C533.1 L512.2 U2.D11 | length 1162.4
  Top Layer w6.3: v1(2161.27,2224.42) C4.1@2206.47,2224.42 ; U2.D11@2603.53,1732.12 v2(2619.28,1747.86)
  SIGNAL 2 w4.5: v1(2161.27,2224.42) 2136.2,2224.42 2103.49,2191.7 2103.49,2008.49 2247.48,1864.49 2247.48,1714.38 2292.78,1669.08 2562.7,1669.08 2589.98,1696.35 2589.98,1727.45 2608.91,1746.38 2617.8,1746.38 v2(2619.28,1747.86)
  Bottom Layer w6.3: v1(2161.27,2224.42) L512.2@2206.47,2224.42
VCC18A_LVDS: C24.2 C524.1 C527.1 C529.1 C530.1 C531.1 C532.1 C538.1 C543.1 C544.1 C546.1 L521.2 U2.B1 U2.B18 U2.C4 U2.C6 U2.C15 U2.D3 U2.D5 U2.D14 U2.D16 U2.E13 U2.F7 U2.F8 U2.F10 U2.F12 | length 415.5
  Top Layer w10: v2(2272.83,1810.86) U2.B1@2288.57,1795.11 ; v2(2335.82,1747.86) U2.D3@2351.57,1732.12 ; v2(2367.31,1779.36) U2.C4@2383.06,1763.61 ; v2(2398.81,1747.86) U2.D5@2414.56,1732.12 ; v2(2430.31,1779.36) U2.C6@2446.05,1763.61 ; v2(2461.8,1684.87) U2.F7@2477.55,1669.12 ; v2(2493.3,1684.87) U2.F8@2509.05,1669.12 ; v2(2556.29,1684.87) U2.F10@2572.04,1669.12 ; U2.F12@2635.03,1669.12 v2(2650.78,1684.87) ; U2.E13@2666.53,1700.62 v2(2682.27,1716.37) ; U2.D14@2698.02,1732.12 v2(2713.77,1747.86) ; U2.C15@2729.52,1763.61 v2(2745.27,1779.36) ; U2.D16@2761.01,1732.12 v2(2776.76,1747.86) ; U2.B18@2824.01,1795.11 v2(2847.28,1795.11)
  Top Layer w15: v1(2888.29,1626.13) C24.2@2927.1,1626.13
  Bottom Layer w15: C527.1@2823.35,1797.86 2844.52,1797.86 v2(2847.28,1795.11)
  Bottom Layer w30: v1(2888.29,1626.13) L521.2@2927.1,1626.13
VCC33A_LVDS: C583.1 C584.1 C585.1 C586.1 C588.1 L524.1 U2.R11 U2.R13 U2.R15 U2.T3 U2.T4 U2.T8 U2.T10 U2.T12 U2.T14 U2.V16 | length 451.8
  Top Layer w10: v2(2335.82,1338.42) U2.T3@2351.57,1354.16 ; v2(2368.21,1338.42) 2368.21,1338.86 U2.T4@2383.06,1353.71 ; v2(2493.3,1338.42) U2.T8@2509.05,1354.16 ; U2.T10@2572.04,1354.16 v2(2587.79,1338.42) ; U2.R11@2603.53,1385.66 v2(2619.28,1369.91) ; U2.T12@2635.03,1354.16 v2(2650.78,1338.42) ; U2.R13@2666.53,1385.66 2666.53,1385.43 2681.81,1370.14 v2(2681.81,1369.91) ; U2.T14@2698.02,1354.16 v2(2713.77,1338.42) ; U2.R15@2729.52,1385.66 v2(2745.27,1369.91) ; v2(2761.01,1255.26) U2.V16@2761.01,1291.17
  Bottom Layer w10: v2@2587.79,1338.61 C583.1@2617.18,1338.61 ; v2(2619.28,1369.91) 2619.28,1368.29 2617.18,1366.18 C583.1@2617.18,1338.61 ; v2(2650.78,1338.42) 2650.68,1338.51 2617.27,1338.51 C583.1@2617.18,1338.61 ; C588.1@2761.01,1279.52 v2(2761.01,1255.26) 2761.01,1224.76 2776.81,1208.96 L524.1@2820.94,1208.96
VIN: C571.1 J5.1 L5.1
  other v1: 4338.63,1344.61 4391.38,1344.61 4391.86,1385.55
VIN_MAIN: C23.1 C31.2 C37.2 C41.1 L5.2 R540.2 R563.2 U5.2 U5.10 | length 146.3
  Top Layer w15: v1(4163.31,1236.38) C37.2@4163.31,1272.09
  Bottom Layer w20: 3916.33,965.59 v1(3932.75,949.17) 3932.75,982.02 3916.33,965.59
  Bottom Layer w23.5: R563.2@3885.03,965.59 3916.33,965.59
  other v1: 3932.75,982.88 4124.19,1085.82 4160.4,1085.82 4196.61,1085.82 4173.61,1313.99 4178.52,1451.78 4174.62,1526.64 4214.62,1526.64 4174.62,1570.92 4214.15,1570.92
VRESET_FIL: C49.1 C600.1 R55.2 R57.2 R566.2 | length 314.9
  Top Layer w6.3: R55.2@4197.29,856.62 C49.1@4285.15,856.62 v1(4285.15,806.42) R57.2@4285.15,767.62
  Bottom Layer w6.3: R566.2@4197.29,856.61 C600.1@4285.15,856.61 v1(4285.15,806.42)
VSYNC: R538.2 TP2.1 U2.J18 | length 4213.6
  Top Layer w6.3: U2.J18@2824.13,1574.76 v2(2852.49,1574.76)
  SIGNAL 4 w4.5: v1(1646.45,1427.84) 1646.45,1394.19 1661.47,1379.17 1791.25,1379.17 1802.06,1389.99 1802.06,1468.15 1792.93,1477.29 1755.95,1477.29 1746.94,1486.3 1746.94,1534.56 1753.98,1541.6 1805.67,1541.6 1817.36,1553.29 1817.36,1616.76 1838.61,1638.01 1873.1,1638.01 2024.62,1789.54 2286.86,1789.54 2315.11,1817.79 2515.9,1817.79 2540.67,1793.02 2540.67,1455.56 2556.59,1439.65 2556.59,1369.07 2571.5,1354.16 2820.97,1354.16 2836.99,1370.18 2891.36,1370.18 2925.82,1404.64 2925.82,1535.27 2886.33,1574.76 v2(2852.49,1574.76)
  SIGNAL 2 w4.5: TP2.1@590.93,2342.8 590.93,2288.95 751.18,2128.69 1439.48,2128.69 1524.02,2044.16 1524.02,1550.26 v1(1646.45,1427.84)
  Bottom Layer w6.3: v1(1646.45,1427.84) R538.2@1646.45,1463.04
VSYNC_S: R538.1 U501.47 | length 213.4
  Bottom Layer w6.3: U501.47@1510.53,1641.15 1555.33,1641.15 1646.45,1550.03 R538.1@1646.45,1510.28
pads on no net: FID1.1 FID2.1 FID3.1 FID4.1 FID5.1 FID6.1 J1.33 J1.34 J1.37 J4.13 J4.14 J9.MH1 J9.MH2 U2.C9 U2.D8 U2.E15 U2.E16 U2.E17 U2.E18 U2.F15 U2.F16 U2.F17 U2.F18 U2.G15 U2.G17 U2.G18 U2.H15 U2.H16 U2.H17 U2.J3 U2.J4 U2.K1 U2.P4 U2.P7 U2.R9 U2.R10 U2.U2 U2.U10 U2.U11 U2.U12 U2.U13 U2.U14 U2.V10 U2.V11 U2.V12 U2.V13 U2.V14 U8.1 U11.2 U11.9 U11.10 U11.18 U11.21 U11.22 U11.25 U11.26 U11.27 U11.30 U11.31 U11.33 U13.1 U15.1 U17.3@549.37,257.02 U17.5 U17.6 U17.7 U17.8@549.37,289.89 U17.9 U17.10 U500.7@3812.09,2206.85 U500.7@3856.97,2206.85 U501.8 U501.40 U501.41 U501.42 U501.49 U501.50 U501.51 U501.52 U501.53 U501.54 U501.55 U501.56 U501.59 U501.60 U501.61 U501.62 U501.63 U501.64 U501.65 U501.66 U501.69 U501.70 U501.71 U501.72 U501.73 U501.74 U501.75 U501.77 U504.7@3881.47,1871.95 U504.7@3881.47,1907.38 U508.4 U508.5 U508.6 U508.11 U508.12 U508.13 U508.14 U509.A1 U509.A2 U509.C1 U509.C2 U512.3@1420.73,389.93 U512.6 U512.7 U512.8@1387.86,389.93 U512.9 U512.10 U513.3@3437.55,388.98 U513.6 U513.7 U513.8@3437.55,421.85 U513.9 U513.10

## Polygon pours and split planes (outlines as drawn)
DMD_VRST on SIGNAL 3 "NONET_L-01_P-001" (solid, remove dead copper, pour order 334): 4099.86,499.87 4253.29,499.61 4316.84,563.16 4316.84,2066.39 3867.33,2515.91 3295.81,2515.91 3268.93,2489.02 3268.93,2393.14 3285.8,2376.27 3676.97,2376.27 4020.05,2033.19 4020.05,579.68
VCC11A_DDI on SIGNAL 3 "SIGNAL_3_VCC11A_DDI_P305" (solid, remove dead copper, pour order 305): 2317.61,1916.86 2331.89,1931.13 2837.96,1931.13 2963.19,1805.9 2963.19,1490.22 2934.76,1461.78 2810.88,1461.78 2790.06,1482.6 2790.06,1532.14 2781.55,1540.64 2336.35,1540.64 2317.61,1559.38
V_DVI_DVDD on SIGNAL 3 "SIGNAL_3_V_DVI_DVDD_P306" (solid, remove dead copper, pour order 306): 1613.53,2142.42 1613.53,1477.72 1515.4,1379.59 1139.84,1379.59 1027,1492.43 1027,2157.05 1067.96,2198.01 1557.93,2198.01
VCC33A_LVDS on SIGNAL 3 "SIGNAL_3_VCC33A_LVDS_P304" (solid, remove dead copper, pour order 304): 2835.92,1234.44 2835.92,1372.95 2820.52,1388.34 2333.67,1388.34 2317.37,1372.04 2317.37,1231.23 2341.31,1207.3 2808.78,1207.3
DMD_VRST on Top Layer "NONET_L-01_P-001" (solid, remove dead copper, pour order 336): 4320.42,508.41 4169.05,508.41 4152.2,525.26 4152.2,565.48 4165.25,578.52 4319.18,578.52 4330.98,566.73 4330.98,517.87 4321.37,508.26
V_DVI_AVDD on Top Layer "NONET_L-01_P-001" (solid, remove dead copper, pour order 330): 885.58,1754.82 925.77,1754.82 928.73,1751.87 928.73,1667.98 925.73,1664.98 828.67,1664.98 806.58,1687.07 714.13,1687.07 709.65,1691.55 709.65,1753.18 710.64,1754.16 833.26,1754.16 851.12,1736.31 867.07,1736.31
GND on Top Layer "NONET_L-01_P-001" (solid, remove dead copper, pour order 328): 2635.4,510.06 2477.11,510.06 2469.68,502.63 2469.68,268.39 2478.46,259.61 2634.15,259.61 2643.7,269.17 2643.7,501.76
GND on Top Layer "NONET_L-01_P-001" (solid, remove dead copper, pour order 327): 1902.01,510.06 2060.31,510.06 2067.73,502.63 2067.73,268.39 2058.95,259.61 1903.27,259.61 1893.71,269.17 1893.71,501.76
P3P3V_REG on Top Layer "TOP_LAYER_P3P3V_REG_P197" (solid, remove dead copper, pour order 197): 3655.78,1670.96 3622.1,1670.96 3619.14,1673.92 3619.14,1713.76 3624.46,1719.08 3696.18,1719.08 3737.42,1677.84 3820.1,1677.84 3830.88,1688.62 3830.88,1766.83 3818.25,1779.46 3774.19,1779.46 3739.53,1814.12 3667.2,1814.12 3660.9,1820.42 3660.9,1854.29 3664.35,1857.74 3783.5,1857.74 3797.43,1843.8 4066.93,1843.8 4087.04,1823.69 4087.04,1577.64 4073.49,1564.09 3672.08,1564.09 3660.9,1575.28 3660.9,1665.84
N8V_FIL on Top Layer "NONET_L-01_P-001" (solid, remove dead copper, pour order 319): 4544.78,572.33 4379.92,572.33 4374.65,567.06 4374.65,514.33 4379.89,509.08 4451.46,509.08 4542.88,509.08 4549.66,515.87 4549.66,567.44
N8V_FIL on Top Layer "NONET_L-01_P-001" (solid, remove dead copper, pour order 317): 4362.05,1031.03 4356.28,1025.26 4356.28,971.55 4360.05,967.78 4542.88,967.78 4549.66,974.57 4549.66,1026.15 4544.78,1031.03
N8V on Top Layer "NONET_L-01_P-001" (solid, remove dead copper, pour order 315): 4339.25,1053.34 4251.86,1053.34 4211.54,1013.01 4034.31,1013.01 4029.57,1008.27 4029.57,950.33 4037.36,942.54 4163.44,942.54 4183.15,962.25 4236.99,962.25 4277.38,1002.64 4293.35,1002.64 4307.63,988.36 4338.5,988.36 4340.87,990.73 4340.87,1051.71
NetD1_2 on Top Layer "NONET_L-01_P-001" (solid, remove dead copper, pour order 170): 4092.73,2198.58 4092.73,2082.27 4101.71,2073.29 4238.39,2073.29 4244.19,2079.08 4244.19,2206.05 4236.72,2213.52 4107.66,2213.52
DMD_VBIAS on Top Layer "TOP_LAYER_DMD_VBIAS_P215" (solid, remove dead copper, pour order 215): 3687.47,740.04 3747.49,740.04 3754.26,733.27 3754.26,676.73 3734.11,656.59 3697.28,656.59 3683.4,670.47 3683.4,735.97
P1P1V on Top Layer "TOP_LAYER_P1P1V_P209" (solid, remove dead copper, pour order 209): 3112.41,1630.56 3283.57,1630.56 3288.82,1625.31 3288.82,1528.74 3280.02,1519.95 3112.31,1519.95 3107.02,1525.23 3107.02,1625.17
GND on Top Layer "TOP_LAYER_GND_P202" (solid, remove dead copper, pour order 202): 1567.67,805.53 1562.99,800.84 1562.99,696.35 1574.26,685.08 1674.75,685.08 1685.16,695.49 1685.16,799.78 1679.41,805.53
GND on Top Layer "TOP_LAYER_GND_P201" (solid, remove dead copper, pour order 201): 644.2,1015.33 639.1,1020.43 586.27,1020.43 582.17,1016.33 582.17,952.49 584.81,949.85 640.7,949.85 644.2,953.34
V_DVI_PVDD on Top Layer "TOP_LAYER_V_DVI_PVDD_P226" (solid, remove dead copper, pour order 226): 928.13,1981.74 924.26,1977.87 672.75,1977.87 668.33,1982.29 668.33,2045.52 672.43,2049.62 922.99,2049.62 928.13,2044.48
P3P3V on Top Layer "TOP_LAYER_P3P3V_P255" (solid, remove dead copper, pour order 255): 1393.99,1535.19 1473.15,1535.19 1479.87,1528.47 1479.87,1417.99 1472.44,1410.57 1392.65,1410.57 1388.9,1414.32 1388.9,1530.1
V_DVI_OVDD on Top Layer "TOP_LAYER_V_DVI_OVDD_P254" (solid, remove dead copper, pour order 254): 1352.6,1535.37 1285.81,1535.37 1277.78,1527.34 1277.78,1415.38 1282.58,1410.57 1357.22,1410.57 1360.98,1414.32 1360.98,1526.99
V_DVI_DVDD on Top Layer "TOP_LAYER_V_DVI_DVDD_P253" (solid, remove dead copper, pour order 253): 1073.42,1535.21 1155.14,1535.21 1166.32,1524.03 1166.32,1418.66 1157.11,1409.45 1068.72,1409.45 1064.42,1413.75 1064.42,1525.99
GND on Top Layer "TOP_LAYER_GND_P252" (solid, remove dead copper, pour order 252): 1052.92,2089.67 1124.2,2089.67 1132.89,2080.98 1132.89,2062.88 1144.72,2051.04 1275.78,2051.04 1289.74,2065.01 1289.74,2085.75 1293.66,2089.67 1345.86,2089.67 1349.42,2086.1 1349.42,2061.52 1359.9,2051.04 1439.57,2051.04 1455.24,2035.36 1478.91,2035.36 1482.45,2031.97 1482.45,2002.16 1475.46,1995.17 1455.94,1995.17 1445.86,1985.09 1445.86,1848.72 1456.26,1838.31 1479.63,1838.33 1482.45,1835.51 1482.45,1585.76 1447.24,1550.54 971.41,1550.54 942.85,1579.11 942.85,2027.47 973.26,2057.89 973.26,2089.14 981.99,2097.87 1044.72,2097.87
DVI_5V on Top Layer "TOP_LAYER_DVI_5V_P227" (solid, remove dead copper, pour order 227): 292.58,1843.82 292.58,1993.7 313.13,2014.25 384.19,2014.25 389.87,2019.93 389.87,2088.42 384.07,2094.22 220.7,2094.22 207.46,2080.98 207.46,1843.27 213.88,1836.85 285.61,1836.85
P6P5V on Top Layer "NONET_L-01_P-001" (solid, remove dead copper, pour order 165): 3829.42,860.59 3829.42,819.79 3836.77,812.44 3836.77,789.02 3838.33,787.46 3863.6,787.46 3865.13,788.99 3865.13,860.4 3861.47,864.06 3832.9,864.06
GND on Top Layer "TOP_LAYER_GND_P248" (solid, remove dead copper, pour order 248): 3894.51,1248.25 3996.76,1248.25 4004.14,1240.86 4004.14,1120.08 3995.96,1111.9 3893.53,1111.9 3887.84,1117.59 3887.84,1241.56
VIN_MAIN on Top Layer "TOP_LAYER_VIN_MAIN_P175" (solid, remove dead copper, pour order 175): 4210.46,1287.61 4210.46,1078.96 4203.57,1072.06 4118.89,1072.06 4111.87,1079.08 4111.87,1218.88 4141.61,1248.62 4141.61,1306.78 4169.03,1334.21 4169.03,1358.1 4172.91,1361.97 4185.9,1361.97 4189.66,1358.21 4189.66,1308.41
GND on Top Layer "TOP_LAYER_GND_P225" (solid, remove dead copper, pour order 225): 2877.84,247.64 2877.84,458.22 2887.03,467.41 2948.03,467.41 2957.64,457.79 2957.64,361.46 3079.02,240.09 3079.02,25.26 3053.76,0 2691.93,0 2670.75,21.18 2670.75,208.23 2685.66,223.14 2853.34,223.14
GND on Top Layer "TOP_LAYER_GND_P224" (solid, remove dead copper, pour order 224): 4413.34,867.4 4814.09,867.4 4814.09,329.26 4811.38,326.55 4583.72,326.55 4570.81,339.46 4570.81,572.55 4552,591.36 4388.08,591.36 4380.56,598.88 4380.56,834.62
VIN on Top Layer "TOP_LAYER_VIN_P172" (solid, remove dead copper, pour order 172): 4310.45,1395.62 4310.45,1335.13 4315.29,1330.29 4539.37,1330.29 4543.64,1334.56 4543.64,1395.39 4538.78,1400.26 4315.09,1400.26
GND on Top Layer "TOP_LAYER_GND_P223" (solid, remove dead copper, pour order 223): 4577.6,1346.1 4544.38,1312.88 4376.79,1312.88 4369.2,1305.29 4369.2,1063.52 4380.77,1051.94 4803.15,1051.94 4803.15,1319.13 4776.18,1346.1
P1P8V on Top Layer "NONET_L-01_P-001" (solid, remove dead copper, pour order 218): 2434.9,2423.37 2431.04,2419.51 2431.04,2374.93 2434.68,2371.29 2434.78,2371.39 2493.81,2371.39 2497.01,2374.59 2497.01,2419.9 2493.54,2423.37
P6P5V on Top Layer "TOP_LAYER_P6P5V_P212" (solid, remove dead copper, pour order 212): 3458.58,620.36 3463.3,625.08 3531.86,625.08 3536.65,620.29 3536.65,587.88 3531.21,582.43 3498.8,582.43 3490.75,574.39 3462.6,574.39 3458.58,578.41
NetL520_1 on Top Layer "TOP_LAYER_NETL520_1_P204" (solid, remove dead copper, pour order 204): 3431.73,1617.4 3479.14,1617.4 3481.24,1619.49 3481.24,1667.57 3479,1669.81 3430.71,1669.81 3428.33,1667.43 3428.33,1620.79
NetL518_1 on Top Layer "TOP_LAYER_NETL518_1_P203" (solid, remove dead copper, pour order 203): 3431.73,1791.59 3479.14,1791.59 3481.24,1789.5 3481.24,1741.42 3479,1739.17 3430.71,1739.17 3428.33,1741.55 3428.33,1788.19
P1P8V on Top Layer "NONET_L-01_P-001" (solid, remove dead copper, pour order 169): 4060.9,2371.39 4008.39,2371.39 4005.2,2374.59 4005.2,2419.9 4008.67,2423.37 4059.94,2423.37 4064.24,2419.08 4064.24,2374.72
GND on Top Layer "TOP_LAYER_GND_P199" (solid, remove dead copper, pour order 199): 3767.9,1763.99 3811.88,1763.99 3815.15,1760.72 3815.15,1695.71 3812.63,1693.18 3746.96,1693.18 3705.66,1734.48 3652.14,1734.48 3647.06,1739.57 3647.06,1793.08 3652.58,1798.61 3733.28,1798.61
NetC38_1 on Top Layer "TOP_LAYER_NETC38_1_P174" (solid, remove dead copper, pour order 174): 4160.26,1396.35 4165.06,1391.56 4201.52,1391.56 4203.17,1389.91 4203.17,1379.96 4201.39,1378.19 4166.27,1378.19 4161.66,1373.57 3885.11,1373.57 3875.9,1382.79 3875.9,1496.03 3881.41,1501.55 4085.84,1501.55 4093.97,1493.41 4093.97,1425.14 4122.76,1396.35
P3P3V on Top Layer "NONET_L-01_P-001" (solid, remove dead copper, pour order 168): 3497.06,1849.23 3500.35,1852.52 3616.98,1852.52 3621.38,1848.12 3621.38,1804.62 3616.35,1799.6 3501.19,1799.6 3497.06,1803.73
NetR9_1 on Top Layer "NONET_L-01_P-001" (solid, remove dead copper, pour order 164): 3595.89,1867.59 3502.33,1867.59 3499.02,1870.9 3499.02,1891.74 3502.06,1894.78 3595.43,1894.78 3597.25,1892.95 3597.25,1868.96
NetC48_1 on Top Layer "NONET_L-01_P-001" (solid, remove dead copper, pour order 166): 3819.31,904.43 3825.85,897.88 3852.31,897.88 3855.13,900.71 3855.13,971.8 3852.8,974.13 3820.96,974.13 3819.31,972.48
P6P5V on Top Layer "NONET_L-01_P-001" (solid, remove dead copper, pour order 173): 3928.32,2313.48 3916.71,2301.87 3916.71,2194.59 3916.71,2093.23 3925.38,2084.7 4013.89,2084.7 4024.94,2095.76 4024.94,2305.49 4016.95,2313.48
VIN_MAIN on Top Layer "TOP_LAYER_VIN_MAIN_P176" (solid, remove dead copper, pour order 176): 4310.37,1431.82 4310.37,1474.74 4299.69,1485.41 4209.57,1485.41 4199.13,1474.96 4199.13,1459.58 4188.78,1449.23 4188.78,1409.75 4185.88,1406.85 4171.5,1406.85 4168.91,1409.44 4168.91,1446.96 4161.18,1454.69 4161.18,1577.15 4170.63,1586.6 4379.14,1586.6 4389.7,1576.03 4389.7,1432.4 4385.97,1428.66 4313.52,1428.66
GND on Top Layer "TOP_LAYER_GND_P178" (solid, remove dead copper, pour order 178): 4411.98,1767.26 4803.15,1767.26 4803.15,1428.95 4413.14,1428.95 4407.52,1434.58 4407.52,1762.8
DMD_VOFS on SIGNAL 2 "NONET_L-01_P-001" (solid, remove dead copper, pour order 338): 2541.22,2411.82 2541.22,2520.24 2572.95,2551.98 3943.27,2551.98 3985.09,2510.15 3985.09,2419.84 3952.25,2386.99 2715.28,2386.99 2566.04,2386.99
VCC3IO_COSC on SIGNAL 2 "SIGNAL_2_VCC3IO_COSC_P303" (solid, remove dead copper, pour order 303): 2877.86,1651.29 2908.84,1651.29 2914.3,1656.54 2914.3,1725.66 2905.67,1734.29 2611.31,1734.29 2601.37,1724.35 2601.37,1613.16 2610.45,1604.08 2740.38,1604.08 2771.82,1635.52 2862.09,1635.52
VCC11A_LVDS on SIGNAL 2 "SIGNAL_2_VCC11A_LVDS_P301" (solid, remove dead copper, pour order 301): 2569.58,1567.4 2569.58,1355.31 2573.38,1351.5 2728.08,1351.5 2732.2,1355.62 2732.2,1376.87 2738.85,1383.55 2813.14,1383.55 2821.32,1375.37 2821.32,1313.68 2830.45,1304.55 2962.86,1304.55 2971.9,1313.58 2971.9,1570.57 2949.38,1593.08 2770.45,1593.08 2754.17,1576.8 2578.98,1576.8
SPI0_DIR1 on SIGNAL 2 "SIGNAL_2_SPI0_DIR1_P302" (solid, remove dead copper, pour order 302): 953.2,692.08 825.34,692.08 817.92,699.49 817.92,722.78 764.88,775.83 764.88,1109.62 783.41,1128.16 942.95,1128.16 963.97,1107.14 963.97,702.86
P1P8V on Bottom Layer "BOTTOM_LAYER_P1P8V_P251" (solid, remove dead copper, pour order 251): 2512.61,2405.13 2494.97,2422.77 2435.14,2422.77 2429.65,2417.28 2429.65,1927.31 2429.65,1855.88 2435.62,1849.91 2533.82,1849.91 2539.61,1855.71 2539.61,1929.5 2512.61,1956.5
P3P3V on Bottom Layer "NONET_L-01_P-001" (solid, remove dead copper, pour order 331): 2609.86,1142.11 2604.54,1147.44 2399.28,1147.44 2397.45,1145.6 2397.45,1087.52 2403.55,1081.42 2602.14,1081.42 2609.86,1089.14
DMD_VOFS on Bottom Layer "BOTTOM_LAYER_DMD_VOFS_P211" (solid, remove dead copper, pour order 211): 3568.92,629.27 3707.54,629.27 3710.46,626.35 3710.46,590.8 3706.34,586.69 3673.85,586.69 3660.72,573.57 3569.91,573.57 3566.51,576.96 3566.51,626.86
DMD_VBIAS on Bottom Layer "BOTTOM_LAYER_DMD_VBIAS_P214" (solid, remove dead copper, pour order 214): 3795.34,650.56 3690.4,650.57 3686.7,654.27 3686.7,744.59 3688.68,746.58 3793.43,746.58 3802.01,738 3802.01,657.23
N8V_FIL on Bottom Layer "NONET_L-01_P-001" (solid, remove dead copper, pour order 321): 4389.83,1031.85 4451.91,1031.85 4454.97,1028.79 4454.97,973.11 4451.23,969.36 4391.87,969.36 4385.77,975.46 4385.77,1027.79
N8V_FIL on Bottom Layer "NONET_L-01_P-001" (solid, remove dead copper, pour order 320): 4381.4,573.15 4436.91,573.15 4439.97,570.09 4439.97,514.4 4436.23,510.66 4382.82,510.66 4377.08,516.4 4377.08,568.83
GND on Bottom Layer "BOTTOM_LAYER_GND_P249" (solid, remove dead copper, pour order 249): 3991.56,1267.56 3885.72,1267.56 3882.33,1264.17 3882.33,1215.92 3903.39,1194.86 3903.39,1033.03 3910,1026.42 4002.41,1026.42 4018.61,1042.61 4018.61,1072.42 3997.5,1093.53 3997.5,1261.62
